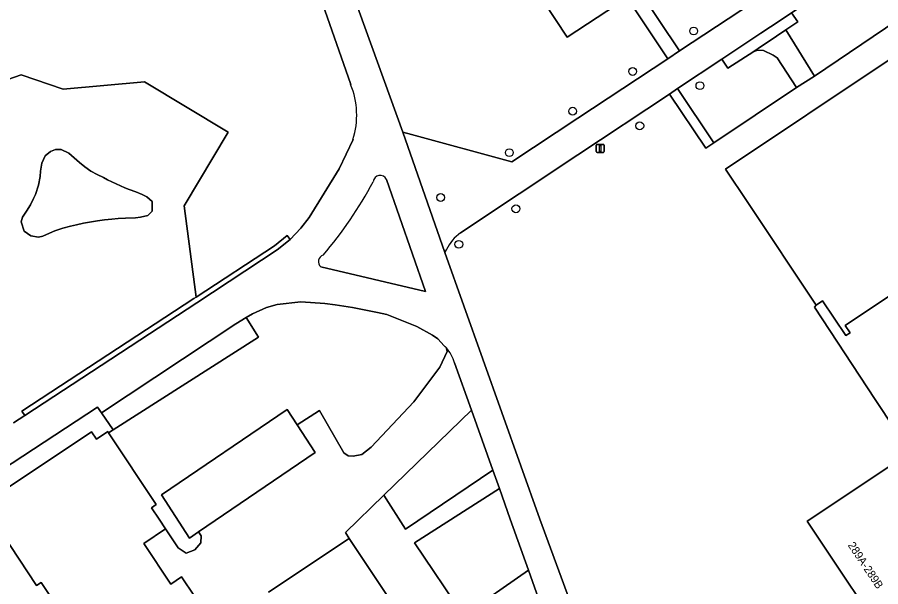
# Model space of a CAD drawing. Extents: x 161483 to 162250, y 379484 to 380833.
# Drawn here: x 161929.9 to 162037.8, y 379991.6 to 380062.8 of the extents above; entities that cross this region are included whole.
import ezdxf

# ---------------------------------------------------------------- set-up
doc = ezdxf.new("R2010")
doc.units = 0
for name, color, linetype in [('IMGEO_Boom', 7, 'Continuous'), ('IMGEO_Erf', 7, 'Continuous'), ('IMGEO_Gemengd_bos', 7, 'Continuous'), ('IMGEO_Groenvoorziening', 7, 'Continuous'), ('IMGEO_Haag', 7, 'Continuous'), ('IMGEO_Lichtmast', 7, 'Continuous'), ('IMGEO_Loofbos', 7, 'Continuous'), ('IMGEO_Meer_plas_ven_vijver', 7, 'Continuous'), ('IMGEO_Pand', 7, 'Continuous'), ('IMGEO_Pand_nummerreeks', 7, 'Continuous'), ('IMGEO_Parkeervlak_gesloten', 7, 'Continuous'), ('IMGEO_Rijbaan_lokaal_gesloten', 7, 'Continuous'), ('IMGEO_Rijbaan_lokaal_open', 7, 'Continuous'), ('IMGEO_Verkeerseiland_open', 7, 'Continuous'), ('IMGEO_Voetpad_open', 7, 'Continuous')]:
    doc.layers.add(name, color=color, linetype=linetype)

msp = doc.modelspace()

# ---------------------------------------------------------------- linework, layer by layer
at = {"layer": 'IMGEO_Boom'}
for centre in [(162014.47, 380061.04), (162006.85, 380055.99), (162015.25, 380054.21), (161999.34, 380051.02), (162007.73, 380049.19), (161991.43, 380045.84), (161982.84, 380040.23), (161992.25, 380038.82), (161985.11, 380034.38)]:
    msp.add_circle(centre, 0.489, dxfattribs=at)
at = {"layer": 'IMGEO_Erf'}
for points in [[(162029.55, 380026.53), (162029.79, 380026.79), (162021.23, 380039.61), (162018.45, 380043.77), (162038.91, 380057.44), (162045.63, 380047.39), (162048.58, 380049.35), (162044.17, 380055.95), (162046.56, 380057.55), (162045.8, 380058.69), (162043.84, 380057.38), (162042.61, 380059.22), (162042.18, 380058.93), (162039.88, 380062.36), (162029.59, 380055.41), (162027.31, 380053.98), (162016.99, 380047.07), (162015.98, 380046.39), (162011.43, 380053.16), (162000, 380045.56), (161985.34, 380035.8)], [(161983.56, 380033.74), (161983.36, 380033.34), (161995.24, 380000), (162000, 379987.08), (162000.65, 379986.76), (162001.88, 379983.25), (162002.56, 379981.43), (162002.09, 379981.25), (162003.41, 379977.7), (162007.84, 379965.74), (162008.36, 379964.92), (162008.87, 379964.28)], [(162039.61, 380011.29), (162037.16, 380014.99), (162029.55, 380026.53)], [(162039.96, 379982.84), (162028.66, 379999.75), (162041.36, 380008.23)]]:
    msp.add_lwpolyline(points, dxfattribs=at)
msp.add_lwpolyline([(161939.22, 380010.93), (161939.82, 380010.02), (161941.24, 380010.96), (161941.35, 380010.8), (161941.93, 380011.18), (161940.46, 380013.3), (161939.95, 380014.04), (161923.9, 380003.5), (161925.84, 380000.58), (161926.28, 380000.87), (161926.09, 380001.15), (161927.6, 380002.15), (161927.11, 380002.88)], close=True, dxfattribs=at)
msp.add_arc((161988.43, 380031.33), 5.43, 124.6669, 153.7247, dxfattribs=at)
at = {"layer": 'IMGEO_Gemengd_bos'}
for points in [[(162144.07, 380140.86), (162032.06, 380067.54), (162031.6, 380066.58), (162026.7, 380063.32), (162027.47, 380062.18), (162026, 380061.19), (162029.59, 380055.41), (162039.88, 380062.36)], [(161971.6, 380054.37), (161953.18, 380107.14)], [(161921.59, 380052.5), (161930.41, 380055.58), (161935.66, 380053.76), (161945.81, 380054.67), (161956.3, 380048.4), (161950.8, 380039.19), (161952.27, 380027.78), (161962.06, 380034.19), (161963.67, 380035.47), (161964.04, 380034.96), (161965.35, 380036.41), (161966.41, 380037.73), (161970.14, 380043.8), (161971.89, 380047.49)], [(162044.62, 380031.71), (162033.42, 380024.22), (162034.02, 380023.33), (162033.47, 380022.96), (162030.57, 380027.31), (162029.79, 380026.79), (162029.55, 380026.53), (162037.16, 380014.99), (162039.61, 380011.29)]]:
    msp.add_lwpolyline(points, dxfattribs=at)
msp.add_arc((161962.17, 380050.52), 10.18, 342.6887, 22.1913, dxfattribs=at)
at = {"layer": 'IMGEO_Groenvoorziening'}
for points in [[(161974.89, 380096.27), (161971.57, 380101.29), (161961.59, 380097.89), (161961.32, 380097.46), (161961.02, 380096.55), (161966.15, 380081.48), (161978.1, 380048.4), (161979.22, 380048.09), (161991.75, 380044.71), (162000, 380050.16), (162011.23, 380057.58), (162006.16, 380065.24), (161998.66, 380060.29)], [(162029.48, 380069.64), (162030.53, 380069.81), (162035.39, 380073), (162030.24, 380081), (162007.63, 380066.21), (162012.7, 380058.55)], [(161933.14, 380035.4), (161932.58, 380035.28), (161931.63, 380035.42), (161930.81, 380036.01), (161930.42, 380037.19), (161930.6, 380037.78), (161931.09, 380038.54), (161931.57, 380039.31), (161931.97, 380040.09), (161932.19, 380040.6), (161932.57, 380041.76), (161932.78, 380042.85), (161932.84, 380043.51), (161932.98, 380044.51), (161933.4, 380045.43), (161934.07, 380046), (161934.69, 380046.22), (161935.43, 380046.22), (161936.36, 380045.77), (161936.72, 380045.49), (161937.72, 380044.61), (161938.38, 380044.06), (161939.11, 380043.52), (161939.9, 380043.12), (161940.69, 380042.72), (161941.22, 380042.45), (161942.28, 380041.92), (161943.36, 380041.44), (161943.9, 380041.23), (161944.73, 380040.93), (161945.55, 380040.6), (161946.12, 380040.31), (161946.79, 380039.75), (161946.79, 380038.51), (161946.23, 380038), (161945.32, 380037.76), (161944.71, 380037.7), (161943.46, 380037.63), (161942.55, 380037.59), (161941.73, 380037.53), (161940.85, 380037.45), (161939.96, 380037.33), (161938.97, 380037.16), (161938.21, 380037.01), (161937.35, 380036.81), (161936.58, 380036.63), (161935.62, 380036.4), (161934.61, 380036.07), (161933.96, 380035.76)], [(161952.36, 380027.08), (161962.42, 380033.68), (161964.04, 380034.96), (161963.67, 380035.47), (161962.06, 380034.19), (161952.27, 380027.78), (161951.99, 380027.6), (161930.49, 380013.5), (161930.86, 380012.98)], [(161983.52, 380021.47), (161983.45, 380021.55), (161983.38, 380021.62), (161983.3, 380021.69), (161982.51, 380022.56), (161981.83, 380023.04), (161979.86, 380024.12), (161976.12, 380025.61), (161974.94, 380025.85), (161971.81, 380026.47), (161969.68, 380026.82), (161968.36, 380026.99), (161965.35, 380027.17), (161962.43, 380026.86), (161961.08, 380026.47), (161959.34, 380025.7), (161958.53, 380025.21), (161960.08, 380022.78), (161941.93, 380011.18), (161941.35, 380010.8), (161947.3, 380001.84), (161946.7, 380001.44), (161947.66, 380000), (161948.47, 379998.79), (161950.05, 379996.42), (161951.02, 379995.77), (161952.14, 379996.17), (161952.87, 379997.08), (161952.93, 379997.92), (161952.58, 379998.43), (161951.46, 379997.66), (161947.97, 380003.07), (161963.67, 380013.74), (161964.92, 380011.82), (161967.69, 380013.6), (161970.74, 380008.32), (161971.29, 380007.95), (161971.9, 380007.88), (161972.99, 380008.1), (161974.14, 380009.02), (161979.48, 380014.68), (161982.75, 380019.04), (161983.65, 380020.97)], [(161989.35, 380006.16), (161986.68, 380013.64), (161975.73, 380003), (161978.44, 379998.77)], [(161991.55, 380000), (161990.18, 380003.84), (161979.58, 379997.08), (161985.72, 379987.99), (161993.82, 379993.63)]]:
    msp.add_lwpolyline(points, close=True, dxfattribs=at)
for points in [[(161929.44, 380012.06), (161930.86, 380012.98), (161930.49, 380013.5), (161951.99, 380027.6), (161952.27, 380027.78), (161950.8, 380039.19), (161956.3, 380048.4), (161945.81, 380054.67), (161935.66, 380053.76), (161930.41, 380055.58), (161921.59, 380052.5)], [(161948.83, 379967.89), (161951.47, 379969.64), (161940.24, 379986.52), (161937.74, 379984.86), (161932.92, 379992.12), (161932.35, 379991.74), (161926.85, 380000), (161926.28, 380000.87), (161925.84, 380000.58), (161924.97, 380000), (161884.91, 379973.59), (161874.32, 379966.47)]]:
    msp.add_lwpolyline(points, dxfattribs=at)
at = {"layer": 'IMGEO_Haag'}
msp.add_lwpolyline([(161952.36, 380027.08), (161962.42, 380033.68), (161964.04, 380034.96), (161963.67, 380035.47), (161962.06, 380034.19), (161952.27, 380027.78), (161951.99, 380027.6), (161930.49, 380013.5), (161930.86, 380012.98)], close=True, dxfattribs=at)
at = {"layer": 'IMGEO_Lichtmast'}
for p, q in [((162002.3, 380045.97), (162002.3, 380046.77)), ((162002.3, 380046.77), (162002.3, 380045.97)), ((162002.4, 380046.87), (162003.18, 380046.87)), ((162003.18, 380046.87), (162002.4, 380046.87)), ((162003.28, 380046.77), (162003.28, 380045.97)), ((162003.28, 380045.97), (162003.28, 380046.77)), ((162003.18, 380045.87), (162002.4, 380045.87)), ((162002.4, 380045.87), (162003.18, 380045.87))]:
    msp.add_line(p, q, dxfattribs=at)
msp.add_lwpolyline([(162002.71, 380046.74), (162002.87, 380046.74), (162002.87, 380045.99), (162002.71, 380045.99), (162002.71, 380046.74)], dxfattribs=at)
for centre, start, end in [((162002.4, 380046.77), 90, 180), ((162002.4, 380046.77), 90, 180), ((162003.18, 380046.77), 0, 90), ((162003.18, 380046.77), 360, 90), ((162002.4, 380045.97), 180, 270), ((162002.4, 380045.97), 180, 270), ((162003.18, 380045.97), 270, 0), ((162003.18, 380045.97), 270, 0)]:
    msp.add_arc(centre, 0.1, start, end, dxfattribs=at)
at = {"layer": 'IMGEO_Loofbos'}
msp.add_lwpolyline([(162024.89, 380057.69), (162024.41, 380058.04), (162023.18, 380058.62), (162022.48, 380058.66), (162021.97, 380058.48), (162018.75, 380056.39), (162017.99, 380057.53), (162012.46, 380053.84), (162016.99, 380047.07), (162027.31, 380053.98)], close=True, dxfattribs=at)
at = {"layer": 'IMGEO_Meer_plas_ven_vijver'}
msp.add_lwpolyline([(161939.11, 380043.52), (161938.38, 380044.06), (161937.72, 380044.61), (161936.72, 380045.49), (161936.36, 380045.77), (161935.43, 380046.22), (161934.69, 380046.22), (161934.07, 380046), (161933.4, 380045.43), (161932.98, 380044.51), (161932.84, 380043.51), (161932.78, 380042.85), (161932.57, 380041.76), (161932.19, 380040.6), (161931.97, 380040.09), (161931.57, 380039.31), (161931.09, 380038.54), (161930.6, 380037.78), (161930.42, 380037.19), (161930.81, 380036.01), (161931.63, 380035.42), (161932.58, 380035.28), (161933.14, 380035.4), (161933.96, 380035.76), (161934.61, 380036.07), (161935.62, 380036.4), (161936.58, 380036.63), (161937.35, 380036.81), (161938.21, 380037.01), (161938.97, 380037.16), (161939.96, 380037.33), (161940.85, 380037.45), (161941.73, 380037.53), (161942.55, 380037.59), (161943.46, 380037.63), (161944.71, 380037.7), (161945.32, 380037.76), (161946.23, 380038), (161946.79, 380038.51), (161946.79, 380039.75), (161946.12, 380040.31), (161945.55, 380040.6), (161944.73, 380040.93), (161943.9, 380041.23), (161943.36, 380041.44), (161942.28, 380041.92), (161941.22, 380042.45), (161940.69, 380042.72), (161939.9, 380043.12)], close=True, dxfattribs=at)
at = {"layer": 'IMGEO_Pand'}
for points in [[(162038.91, 380057.44), (162018.45, 380043.77), (162021.23, 380039.61), (162029.79, 380026.79), (162030.57, 380027.31), (162033.47, 380022.96), (162034.02, 380023.33), (162033.42, 380024.22), (162044.62, 380031.71)], [(161953.7, 379987.96), (161950.47, 379992.8), (161949.13, 379991.91), (161945.76, 379996.98), (161948.47, 379998.79), (161947.66, 380000), (161946.7, 380001.44), (161947.3, 380001.84), (161941.35, 380010.8), (161941.24, 380010.96), (161939.82, 380010.02), (161939.22, 380010.93), (161927.11, 380002.88), (161927.6, 380002.15), (161926.09, 380001.15), (161926.28, 380000.87), (161926.85, 380000), (161932.35, 379991.74), (161932.92, 379992.12), (161937.74, 379984.86)], [(161982.47, 379981), (161971.42, 379997.61), (161961.32, 379990.89)]]:
    msp.add_lwpolyline(points, dxfattribs=at)
for points in [[(161967.16, 380008.34), (161964.92, 380011.82), (161963.67, 380013.74), (161947.97, 380003.07), (161951.46, 379997.66), (161952.58, 379998.43)], [(162041.36, 380008.23), (162028.66, 379999.75), (162039.96, 379982.84), (162040.65, 379983.29), (162043.63, 379978.83), (162044.27, 379979.25), (162043.61, 379980.24), (162055.09, 379987.91), (162060.57, 379979.71), (162060.98, 379979.99), (162070.88, 379986.6), (162064.77, 379995.74), (162062.2, 379994.03), (162061.62, 379994.89), (162056.1, 380003.11), (162049.16, 380013.44)]]:
    msp.add_lwpolyline(points, close=True, dxfattribs=at)
at = {"layer": 'IMGEO_Parkeervlak_gesloten'}
msp.add_lwpolyline([(161960.08, 380022.78), (161958.53, 380025.21), (161957.25, 380024.43), (161940.46, 380013.3), (161941.93, 380011.18)], close=True, dxfattribs=at)
at = {"layer": 'IMGEO_Rijbaan_lokaal_gesloten'}
for points in [[(161953.18, 380107.14), (161971.6, 380054.37)], [(161984.58, 380019.56), (161986.68, 380013.64), (161989.35, 380006.16), (161990.18, 380003.84), (161991.55, 380000), (161993.82, 379993.63), (161995.33, 379989.38), (161999.67, 379976.34), (162003.41, 379977.7), (162002.09, 379981.25), (162001.46, 379982.97), (162000.38, 379986.05), (162000, 379987.08), (161995.24, 380000), (161983.36, 380033.34), (161978.1, 380048.4), (161966.15, 380081.48), (161961.02, 380096.55)], [(161971.89, 380047.49), (161970.14, 380043.8), (161966.41, 380037.73), (161965.35, 380036.41), (161964.04, 380034.96), (161962.42, 380033.68), (161952.36, 380027.08), (161930.86, 380012.98), (161929.44, 380012.06)], [(161976.07, 380042.49), (161980.96, 380028.46), (161967.88, 380031.57)], [(161923.9, 380003.5), (161939.95, 380014.04), (161940.46, 380013.3), (161957.25, 380024.43), (161958.53, 380025.21), (161959.34, 380025.7), (161961.08, 380026.47), (161962.43, 380026.86), (161965.35, 380027.17), (161968.36, 380026.99), (161969.68, 380026.82), (161971.81, 380026.47), (161974.94, 380025.85), (161976.12, 380025.61), (161979.86, 380024.12), (161981.83, 380023.04), (161982.51, 380022.56), (161983.3, 380021.69), (161983.38, 380021.62), (161983.45, 380021.55), (161983.52, 380021.47)]]:
    msp.add_lwpolyline(points, dxfattribs=at)
msp.add_lwpolyline([(162026, 380061.19), (162023.64, 380059.6), (162022.96, 380059.14), (162021.97, 380058.48), (162022.48, 380058.66), (162023.18, 380058.62), (162024.41, 380058.04), (162024.89, 380057.69), (162027.31, 380053.98), (162029.59, 380055.41)], close=True, dxfattribs=at)
for centre, radius, start, end in [((161962.17, 380050.52), 10.18, 342.6887, 22.1913), ((161975.28, 380042.14), 0.864, 24.3358, 175.6127), ((161928.72, 380066.64), 51.82, 319.549, 331.8645), ((161968.38, 380032.23), 0.826, 106.2556, 232.6483), ((161980.2, 380018.39), 4.53, 14.9029, 42.7831)]:
    msp.add_arc(centre, radius, start, end, dxfattribs=at)
at = {"layer": 'IMGEO_Rijbaan_lokaal_open'}
for points in [[(162144.07, 380140.86), (162145.37, 380141.37), (162146.97, 380142), (162144.62, 380145.45), (162141.7, 380142.85), (162082.94, 380104.25), (162037.16, 380074.16), (162035.39, 380073), (162030.53, 380069.81), (162029.48, 380069.64), (162012.7, 380058.55), (162011.23, 380057.58), (162000, 380050.16), (161991.75, 380044.71), (161979.22, 380048.09), (161978.1, 380048.4), (161983.36, 380033.34), (161983.56, 380033.74)], [(161985.34, 380035.8), (162000, 380045.56), (162011.43, 380053.16), (162012.46, 380053.84), (162017.99, 380057.53), (162022.87, 380060.77), (162025.27, 380062.37), (162026.7, 380063.32), (162031.6, 380066.58), (162032.06, 380067.54), (162144.07, 380140.86)], [(161983.52, 380021.47), (161983.65, 380020.97), (161982.75, 380019.04), (161979.48, 380014.68), (161974.14, 380009.02), (161972.99, 380008.1), (161971.9, 380007.88), (161971.29, 380007.95), (161970.74, 380008.32), (161967.69, 380013.6), (161964.92, 380011.82), (161967.16, 380008.34), (161952.58, 379998.43), (161952.93, 379997.92), (161952.87, 379997.08), (161952.14, 379996.17), (161951.02, 379995.77), (161950.05, 379996.42), (161948.47, 379998.79), (161945.76, 379996.98), (161949.13, 379991.91), (161950.47, 379992.8), (161953.7, 379987.96)], [(161975.73, 380003), (161986.68, 380013.64), (161984.58, 380019.56)], [(161961.32, 379990.89), (161971.42, 379997.61), (161970.94, 379998.34), (161975.73, 380003)]]:
    msp.add_lwpolyline(points, dxfattribs=at)
msp.add_lwpolyline([(162026, 380061.19), (162027.47, 380062.18), (162026.7, 380063.32), (162025.27, 380062.37), (162022.87, 380060.77), (162017.99, 380057.53), (162018.75, 380056.39), (162021.97, 380058.48), (162022.96, 380059.14), (162023.64, 380059.6)], close=True, dxfattribs=at)
for centre, radius, start, end in [((161988.43, 380031.33), 5.43, 124.6669, 153.7247), ((161980.2, 380018.39), 4.53, 14.9029, 42.7831)]:
    msp.add_arc(centre, radius, start, end, dxfattribs=at)
at = {"layer": 'IMGEO_Verkeerseiland_open'}
msp.add_lwpolyline([(161967.88, 380031.57), (161980.96, 380028.46), (161976.07, 380042.49)], dxfattribs=at)
for centre, radius, start, end in [((161975.28, 380042.14), 0.864, 24.3358, 175.6127), ((161928.72, 380066.64), 51.82, 319.549, 331.8645), ((161968.38, 380032.23), 0.826, 106.2556, 232.6483)]:
    msp.add_arc(centre, radius, start, end, dxfattribs=at)
at = {"layer": 'IMGEO_Voetpad_open'}
for points in [[(161974.89, 380096.27), (161998.66, 380060.29), (162006.16, 380065.24), (162011.23, 380057.58), (162012.7, 380058.55), (162007.63, 380066.21)], [(161995.33, 379989.38), (161993.82, 379993.63), (161985.72, 379987.99), (161979.58, 379997.08), (161990.18, 380003.84), (161989.35, 380006.16), (161978.44, 379998.77), (161975.73, 380003), (161970.94, 379998.34), (161971.42, 379997.61), (161982.47, 379981)]]:
    msp.add_lwpolyline(points, dxfattribs=at)
msp.add_lwpolyline([(162012.46, 380053.84), (162011.43, 380053.16), (162015.98, 380046.39), (162016.99, 380047.07)], close=True, dxfattribs=at)

# ---------------------------------------------------------------- texts
at = {"layer": 'IMGEO_Pand_nummerreeks'}
msp.add_text('289A-289B', height=1, rotation=303.7487, dxfattribs=at).set_placement((162033.69, 379996.76))

doc.saveas('drawing.dxf')
